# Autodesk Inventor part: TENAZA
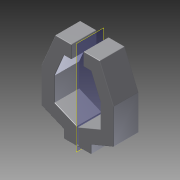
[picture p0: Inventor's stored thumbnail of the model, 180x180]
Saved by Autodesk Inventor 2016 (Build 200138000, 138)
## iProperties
Created: 2012-05
Part Number: TENAZA
Material: Generic
Document SubType Name: Modeling
Designer: julian.chica
Density: 1 g/cm^3
Mass: 435.626 g
Surface Area: 587.73 cm^2
Volume: 435.626 cm^3
Appearance: Default
Author: julian.chica
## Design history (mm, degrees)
sketch "Sketch1"
  geometry: L1 (-12.5, -23)-(-12.5, 23) reference; L2 (37.5, -23)-(-12.5, -23) reference; L3 (37.5, 23)-(37.5, -23) reference; L4 (-12.5, 23)-(37.5, 23) reference; C1 r 20 at (12.5, 0) reference; 1 further point
extrude "Extrusion1" new body sketch "Sketch1" distance "d0" = 2; taper "d1" = 0 deg
sketch "Sketch2"
  geometry: L1 (-37.5, 0)-(-37.5, 2) reference; L2 (12.5, 0)-(12.5, 2) reference; L3 (-37.5, 2)-(-37.5, 15.218); L4 (-37.5, 15.218)-(-78.548, 32.379); L5 (-78.548, 32.379)-(-78.548, 96.175); L6 (-78.548, 96.175)-(-53.135, 156.171); L7 (-53.135, 156.171)-(-23.521, 156.171); L8 (-23.521, 132.171)-(-37.237, 132.171); L9 (-37.237, 132.171)-(-54.548, 91.302); L10 (-54.548, 91.302)-(-54.548, 48.358); L11 (-54.548, 48.358)-(-13.5, 31.197); L12 (-13.5, 31.197)-(-13.5, 2); L13 (-13.5, 2)-(-13.5, 0); L14 (-23.521, 156.171)-(-23.521, 132.171); L15 (-37.5, 0)-(-13.5, 0); 1 further point
  constraints: 26 end point, 4 perpendicular, 3 parallel, 5 other
  dimensions: "d2" = 24 distance between parallel lines of L5 L10
extrude "Extrusion2" join sketch "Sketch2" stored distance "d3" = 2; taper "d4" = 0 deg
workplane "Work Plane1"
  workaxis "Work Axis1"
mirror "Mirror1"
fillet "Fillet1" dims "d6" = 1
body "Solid1"
node "Reference1"
other parameters: "d5" = 0
